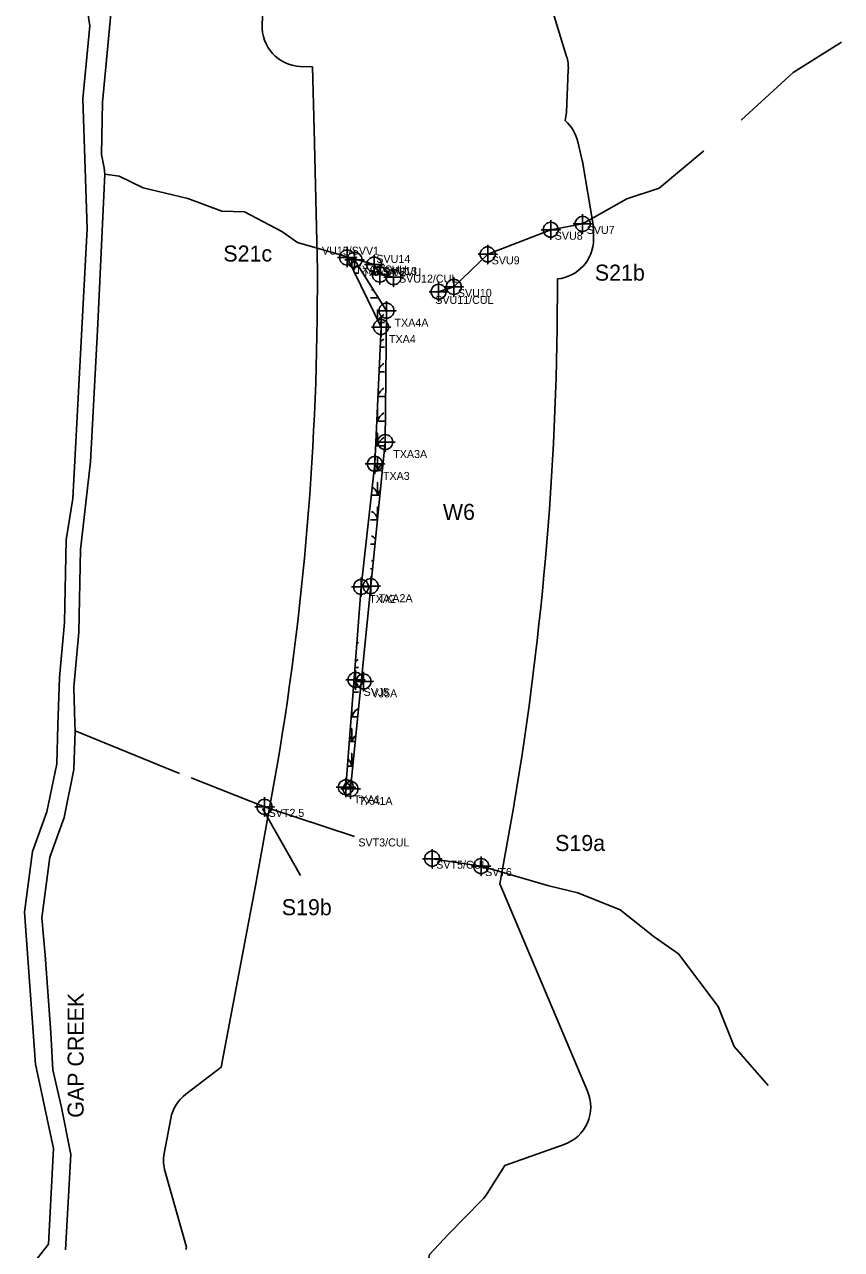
# Model space of a CAD drawing. Extents: x 1253697 to 1278588, y 912189 to 981699.
# Drawn here: x 1262865 to 1263886, y 921586 to 923116 of the extents above; entities that cross this region are included whole.
import ezdxf

# ---------------------------------------------------------------- set-up
doc = ezdxf.new("R2010")
doc.units = 0
for name, color, linetype in [('Default', 7, 'Continuous'), ('Exist Environmental Wetland Boundary', 7, 'Continuous'), ('Exist Environmental Wetland Boundary Cogo Comment', 7, 'Continuous'), ('Exist Environmental Wetland Boundary Cogo Number', 7, 'Continuous'), ('Exist Environmental Wetland Boundary Cogo Point CELL', 7, 'Continuous'), ('Exist Hydro Jurisdictional Stream or Body of Water Mitigable', 7, 'Continuous'), ('Exist Hydro Jurisdictional Stream or Body of Water Mitigable Cogo Comment', 7, 'Continuous'), ('Exist Hydro Jurisdictional Stream or Body of Water Mitigable Cogo Number', 7, 'Continuous'), ('Exist Hydro Jurisdictional Stream or Body of Water Mitigable Cogo Point CELL', 7, 'Continuous'), ('Exist Hydro Swamp or Marsh', 7, 'Continuous')]:
    doc.layers.add(name, color=color, linetype=linetype)

msp = doc.modelspace()

# ---------------------------------------------------------------- linework, layer by layer
at = {"layer": 'Default'}
for p, q in [((1263166.7, 923205.8), (1263162.4, 923115.9)), ((1263166.7, 923205.8), (1263162.4, 923115.9)), ((1263166.7, 923205.8), (1263162.4, 923115.9)), ((1263166.7, 923205.8), (1263162.4, 923115.9)), ((1263542.4, 923006.2), (1263544.8, 923059.2)), ((1263542.4, 923006.2), (1263544.8, 923059.2)), ((1263542.4, 923006.2), (1263544.8, 923059.2)), ((1263542.4, 923006.2), (1263544.8, 923059.2)), ((1263561.8, 922947.5), (1263556.8, 922969.5)), ((1263561.8, 922947.5), (1263556.8, 922969.5)), ((1263561.8, 922947.5), (1263556.8, 922969.5)), ((1263561.8, 922947.5), (1263556.8, 922969.5)), ((1263575.8, 922865.7), (1263562.4, 922944.6)), ((1263575.8, 922865.7), (1263562.4, 922944.6)), ((1263575.8, 922865.7), (1263562.4, 922944.6)), ((1263575.8, 922865.7), (1263562.4, 922944.6)), ((1263576.4, 922847.4), (1263576.5, 922857)), ((1263576.4, 922847.4), (1263576.5, 922857)), ((1263576.4, 922847.4), (1263576.5, 922857)), ((1263576.4, 922847.4), (1263576.5, 922857)), ((1263162.7, 922136.7), (1263210.2, 922053)), ((1263048.1, 921749.3), (1263039.9, 921705.7)), ((1263048.1, 921749.3), (1263039.9, 921705.7)), ((1263048.1, 921749.3), (1263039.9, 921705.7)), ((1263048.1, 921749.3), (1263039.9, 921705.7))]:
    msp.add_line(p, q, dxfattribs=at)
for points in [[(1263542.7, 923076), (1263522.8, 923141.4), (1263517.8, 923304.9), (1263553.3, 923436.7)], [(1263542.7, 923076), (1263522.8, 923141.4), (1263517.8, 923304.9), (1263553.3, 923436.7)], [(1263542.7, 923076), (1263522.8, 923141.4), (1263517.8, 923304.9), (1263553.3, 923436.7)], [(1263542.7, 923076), (1263522.8, 923141.4), (1263517.8, 923304.9), (1263553.3, 923436.7)], [(1263209.9, 923063.5), (1263225, 923062.8), (1263227.4, 922984.9), (1263231.1, 922827.6)], [(1263209.9, 923063.5), (1263225, 923062.8), (1263227.4, 922984.9), (1263231.1, 922827.6)], [(1263209.9, 923063.5), (1263225, 923062.8), (1263227.4, 922984.9), (1263231.1, 922827.6)], [(1263209.9, 923063.5), (1263225, 923062.8), (1263227.4, 922984.9), (1263231.1, 922827.6)], [(1263181.5, 922192.6), (1263153.4, 922037.8), (1263111.1, 921813.4), (1263067, 921779.8)], [(1263181.5, 922192.6), (1263153.4, 922037.8), (1263111.1, 921813.4), (1263067, 921779.8)], [(1263181.5, 922192.6), (1263153.4, 922037.8), (1263111.1, 921813.4), (1263067, 921779.8)], [(1263181.5, 922192.6), (1263153.4, 922037.8), (1263111.1, 921813.4), (1263067, 921779.8)], [(1263569, 921783.6), (1263459.1, 922042.4), (1263477.2, 922142.2)], [(1263569, 921783.6), (1263459.1, 922042.4), (1263477.2, 922142.2)], [(1263569, 921783.6), (1263459.1, 922042.4), (1263477.2, 922142.2)], [(1263569, 921783.6), (1263459.1, 922042.4), (1263477.2, 922142.2)], [(1263443.6, 921655.7), (1263465.6, 921690.5), (1263539.7, 921716.9)], [(1263443.6, 921655.7), (1263465.6, 921690.5), (1263539.7, 921716.9)], [(1263443.6, 921655.7), (1263465.6, 921690.5), (1263539.7, 921716.9)], [(1263443.6, 921655.7), (1263465.6, 921690.5), (1263539.7, 921716.9)], [(1263040.9, 921682.8), (1263067.6, 921588.7), (1263067, 921585.8)], [(1263040.9, 921682.8), (1263067.6, 921588.7), (1263067, 921585.8)], [(1263040.9, 921682.8), (1263067.6, 921588.7), (1263067, 921585.8)], [(1263040.9, 921682.8), (1263067.6, 921588.7), (1263067, 921585.8)], [(1263360.8, 921525), (1263371.4, 921579.3), (1263395, 921604.9), (1263436.9, 921647.3)], [(1263360.8, 921525), (1263371.4, 921579.3), (1263395, 921604.9), (1263436.9, 921647.3)], [(1263360.8, 921525), (1263371.4, 921579.3), (1263395, 921604.9), (1263436.9, 921647.3)], [(1263360.8, 921525), (1263371.4, 921579.3), (1263395, 921604.9), (1263436.9, 921647.3)]]:
    msp.add_lwpolyline(points, dxfattribs=at)
for centre, radius, start, end in [((1263212.3, 923113.4), 50, 177.2304, 267.2304), ((1263212.3, 923113.4), 50, 177.2304, 267.2304), ((1263212.3, 923113.4), 50, 177.2304, 267.2304), ((1263212.3, 923113.4), 50, 177.2304, 267.2304), ((1263494.9, 923061.5), 50, 357.4241, 16.9585), ((1263494.9, 923061.5), 50, 357.4241, 16.9585), ((1263494.9, 923061.5), 50, 357.4241, 16.9585), ((1263494.9, 923061.5), 50, 357.4241, 16.9585), ((1263492.5, 923008.5), 50, 345.4443, 357.4241), ((1263492.5, 923008.5), 50, 345.4443, 357.4241), ((1263492.5, 923008.5), 50, 345.4443, 357.4241), ((1263492.5, 923008.5), 50, 345.4443, 357.4241), ((1263508, 922958.2), 50, 13.0553, 48.9515), ((1263508, 922958.2), 50, 13.0553, 48.9515), ((1263508, 922958.2), 50, 13.0553, 48.9515), ((1263508, 922958.2), 50, 13.0553, 48.9515), ((1263513.1, 922936.2), 50, 9.6038, 13.0553), ((1263513.1, 922936.2), 50, 9.6038, 13.0553), ((1263513.1, 922936.2), 50, 9.6038, 13.0553), ((1263513.1, 922936.2), 50, 9.6038, 13.0553), ((1263526.5, 922857.4), 50, 359.5399, 9.6038), ((1263526.5, 922857.4), 50, 359.5399, 9.6038), ((1263526.5, 922857.4), 50, 359.5399, 9.6038), ((1263526.5, 922857.4), 50, 359.5399, 9.6038), ((1263526.4, 922847.8), 50, 275.5842, 359.5399), ((1263526.4, 922847.8), 50, 275.5842, 359.5399), ((1263526.4, 922847.8), 50, 275.5842, 359.5399), ((1263526.4, 922847.8), 50, 275.5842, 359.5399), ((1259581.3, 922793.3), 3650, 350.5278, 0.538), ((1259581.3, 922793.3), 3650, 350.5278, 0.538), ((1259581.3, 922793.3), 3650, 350.5278, 0.538), ((1259581.3, 922793.3), 3650, 350.5278, 0.538), ((1259581.3, 922793.3), 3950, 350.5223, 0.0692), ((1259581.3, 922793.3), 3950, 350.5223, 0.0692), ((1259581.3, 922793.3), 3950, 350.5223, 0.0692), ((1259581.3, 922793.3), 3950, 350.5223, 0.0692), ((1263428, 922151.1), 50, 349.7208, 350.5223), ((1263428, 922151.1), 50, 349.7208, 350.5223), ((1263428, 922151.1), 50, 349.7208, 350.5223), ((1263428, 922151.1), 50, 349.7208, 350.5223), ((1263097.2, 921740), 50, 127.2474, 169.2814), ((1263097.2, 921740), 50, 127.2474, 169.2814), ((1263097.2, 921740), 50, 127.2474, 169.2814), ((1263097.2, 921740), 50, 127.2474, 169.2814), ((1263522.9, 921764), 50, 289.6297, 22.9949), ((1263522.9, 921764), 50, 289.6297, 22.9949), ((1263522.9, 921764), 50, 289.6297, 22.9949), ((1263522.9, 921764), 50, 289.6297, 22.9949), ((1263089, 921696.4), 50, 169.2814, 195.8576), ((1263089, 921696.4), 50, 169.2814, 195.8576), ((1263089, 921696.4), 50, 169.2814, 195.8576), ((1263089, 921696.4), 50, 169.2814, 195.8576), ((1263401.4, 921682.5), 50, 315.3188, 327.6996), ((1263401.4, 921682.5), 50, 315.3188, 327.6996), ((1263401.4, 921682.5), 50, 315.3188, 327.6996), ((1263401.4, 921682.5), 50, 315.3188, 327.6996)]:
    msp.add_arc(centre, radius, start, end, dxfattribs=at)
at = {"layer": 'Exist Environmental Wetland Boundary'}
msp.add_lwpolyline([(1263268.5, 922824.8), (1263310.8, 922738), (1263303.2, 922567), (1263285.9, 922413.3), (1263266.9, 922163.1), (1263272.8, 922161), (1263297.9, 922414.3), (1263316.1, 922594.3), (1263317.7, 922758.4), (1263277.6, 922821.9)], close=True, dxfattribs=at)
at = {"layer": 'Exist Environmental Wetland Boundary Cogo Point CELL'}
for points in [[(1263268.5, 922836.8), (1263268.5, 922812.8), (1263268.5, 922824.8), (1263280.5, 922824.8), (1263256.5, 922824.8)], [(1263277.6, 922833.9), (1263277.6, 922809.9), (1263277.6, 922821.9), (1263289.6, 922821.9), (1263265.6, 922821.9)], [(1263317.7, 922770.4), (1263317.7, 922746.4), (1263317.7, 922758.4), (1263329.7, 922758.4), (1263305.7, 922758.4)], [(1263310.8, 922750), (1263310.8, 922726), (1263310.8, 922738), (1263322.8, 922738), (1263298.8, 922738)], [(1263316.1, 922606.3), (1263316.1, 922582.3), (1263316.1, 922594.3), (1263328.1, 922594.3), (1263304.1, 922594.3)], [(1263303.2, 922579), (1263303.2, 922555), (1263303.2, 922567), (1263315.2, 922567), (1263291.2, 922567)], [(1263285.9, 922425.3), (1263285.9, 922401.3), (1263285.9, 922413.3), (1263297.9, 922413.3), (1263273.9, 922413.3)], [(1263297.9, 922426.3), (1263297.9, 922402.3), (1263297.9, 922414.3), (1263309.9, 922414.3), (1263285.9, 922414.3)], [(1263279, 922309.2), (1263279, 922285.2), (1263279, 922297.2), (1263291, 922297.2), (1263267, 922297.2)], [(1263289.1, 922307.3), (1263289.1, 922283.3), (1263289.1, 922295.3), (1263301.1, 922295.3), (1263277.1, 922295.3)], [(1263266.9, 922175.1), (1263266.9, 922151.1), (1263266.9, 922163.1), (1263278.9, 922163.1), (1263254.9, 922163.1)], [(1263272.8, 922173), (1263272.8, 922149), (1263272.8, 922161), (1263284.8, 922161), (1263260.8, 922161)]]:
    msp.add_lwpolyline(points, dxfattribs=at)
for centre in [(1263268.5, 922824.8), (1263277.6, 922821.9), (1263317.7, 922758.4), (1263310.8, 922738), (1263316.1, 922594.3), (1263303.2, 922567), (1263285.9, 922413.3), (1263297.9, 922414.3), (1263279, 922297.2), (1263289.1, 922295.3), (1263266.9, 922163.1), (1263272.8, 922161)]:
    msp.add_circle(centre, 9.38, dxfattribs=at)
at = {"layer": 'Exist Hydro Jurisdictional Stream or Body of Water Mitigable'}
msp.add_line((1262928.5, 922233.7), (1263059.2, 922180.1), dxfattribs=at)
for points in [[(1262940.8, 923154.8), (1262946.9, 923114.4), (1262938.1, 923023.2), (1262943.8, 922861.2), (1262925.9, 922523.9), (1262917.2, 922472), (1262915.1, 922369.1), (1262908.9, 922300.3), (1262907, 922240.7), (1262905.6, 922192.4), (1262893.3, 922132.4), (1262875.5, 922082.7), (1262865.3, 922006.9), (1262879.1, 921817.1), (1262901.7, 921711.7), (1262895.1, 921592.4), (1262881.4, 921575)], [(1262916.6, 921585.4), (1262923.2, 921704.6), (1262911.6, 921763.3), (1262900.6, 921810.1), (1262898.4, 921856.2), (1262891.1, 921953.3), (1262886.8, 921999.9), (1262897, 922075.7), (1262914.8, 922125.4), (1262927.1, 922185.3), (1262928.5, 922233.7), (1262928.4, 922242.7), (1262927.1, 922288.2), (1262933.2, 922357), (1262935.4, 922459.9), (1262947.9, 922569.6), (1262956.9, 922742), (1262962, 922849.1), (1262965.7, 922929.1), (1262965, 922936.9), (1262961.7, 922953.6), (1262962.7, 923018.7), (1262975.4, 923151.1)], [(1263886.3, 923093.6), (1263825.7, 923055.7), (1263760.8, 922996.3)], [(1263714.3, 922957.9), (1263658.2, 922911.4), (1263617.9, 922898.1), (1263562.8, 922866.8)], [(1262965.7, 922929.1), (1262983.4, 922926.3), (1263013.7, 922911.9), (1263069.4, 922898.5), (1263112, 922882.8), (1263140.1, 922882), (1263187, 922857.4), (1263206.6, 922843.5), (1263302.2, 922815.9), (1263309.3, 922803.5), (1263326.5, 922800.3)], [(1263382.8, 922782.1), (1263401.8, 922788.1), (1263444.1, 922828.8), (1263522.9, 922859.5), (1263562.8, 922866.8), (1263574.5, 922873.4)], [(1263073.6, 922174.9), (1263165.3, 922138.6), (1263277.5, 922101.7)], [(1263171.3, 922136.6), (1263277.5, 922101.7)], [(1263374.8, 922073.9), (1263435.9, 922064.7), (1263461.8, 922057.1)], [(1263435.9, 922064.7), (1263520.4, 922039.8), (1263556.8, 922031.1), (1263609.5, 922010), (1263652.3, 921976.2), (1263682.6, 921954.9), (1263732.2, 921889.4), (1263752.2, 921839.4), (1263794.8, 921790.6)]]:
    msp.add_lwpolyline(points, dxfattribs=at)
at = {"layer": 'Exist Hydro Jurisdictional Stream or Body of Water Mitigable Cogo Point CELL'}
for points in [[(1263522.9, 922871.5), (1263522.9, 922847.5), (1263522.9, 922859.5), (1263534.9, 922859.5), (1263510.9, 922859.5)], [(1263562.8, 922878.8), (1263562.8, 922854.8), (1263562.8, 922866.8), (1263574.8, 922866.8), (1263550.8, 922866.8)], [(1263444.1, 922840.8), (1263444.1, 922816.8), (1263444.1, 922828.8), (1263456.1, 922828.8), (1263432.1, 922828.8)], [(1263302.2, 922827.9), (1263302.2, 922803.9), (1263302.2, 922815.9), (1263314.2, 922815.9), (1263290.2, 922815.9)], [(1263309.3, 922815.5), (1263309.3, 922791.5), (1263309.3, 922803.5), (1263321.3, 922803.5), (1263297.3, 922803.5)], [(1263326.5, 922812.3), (1263326.5, 922788.3), (1263326.5, 922800.3), (1263338.5, 922800.3), (1263314.5, 922800.3)], [(1263382.8, 922794.1), (1263382.8, 922770.1), (1263382.8, 922782.1), (1263394.8, 922782.1), (1263370.8, 922782.1)], [(1263401.8, 922800.1), (1263401.8, 922776.1), (1263401.8, 922788.1), (1263413.8, 922788.1), (1263389.8, 922788.1)], [(1263165.3, 922150.6), (1263165.3, 922126.6), (1263165.3, 922138.6), (1263177.3, 922138.6), (1263153.3, 922138.6)], [(1263374.8, 922085.9), (1263374.8, 922061.9), (1263374.8, 922073.9), (1263386.8, 922073.9), (1263362.8, 922073.9)], [(1263435.9, 922076.7), (1263435.9, 922052.7), (1263435.9, 922064.7), (1263447.9, 922064.7), (1263423.9, 922064.7)]]:
    msp.add_lwpolyline(points, dxfattribs=at)
for centre in [(1263562.8, 922866.8), (1263522.9, 922859.5), (1263302.2, 922815.9), (1263444.1, 922828.8), (1263309.3, 922803.5), (1263326.5, 922800.3), (1263401.8, 922788.1), (1263382.8, 922782.1), (1263165.3, 922138.6), (1263374.8, 922073.9), (1263435.9, 922064.7)]:
    msp.add_circle(centre, 9.38, dxfattribs=at)
at = {"layer": 'Exist Hydro Swamp or Marsh'}
for p, q in [((1263278, 922805.1), (1263282.8, 922805.1)), ((1263308, 922743.6), (1263315, 922743.6)), ((1263309.6, 922712.8), (1263315, 922712.8)), ((1263308.3, 922682), (1263315, 922682)), ((1263306.9, 922651.2), (1263315, 922651.2)), ((1263297.8, 922497.3), (1263306.3, 922497.3)), ((1263297.8, 922466.6), (1263303.2, 922466.6)), ((1263297.8, 922435.8), (1263300.1, 922435.8)), ((1263280.6, 922343.4), (1263282.8, 922343.4)), ((1263278.3, 922312.7), (1263282.8, 922312.7)), ((1263275.9, 922281.9), (1263282.8, 922281.9))]:
    msp.add_line(p, q, dxfattribs=at)
for points in [[(1263274.2, 922813), (1263274.2, 922820.9), (1263274.2, 922813)], [(1263297.8, 922774.4), (1263306.4, 922774.4), (1263306.4, 922776.3)], [(1263306.4, 922776.3), (1263306.4, 922774.4), (1263307.6, 922774.4)], [(1263306.4, 922746.9), (1263306.4, 922759.4), (1263306.4, 922746.9)], [(1263305.6, 922620.5), (1263306.4, 922620.5), (1263306.4, 922636.2), (1263306.4, 922620.5), (1263315, 922620.5)], [(1263304.2, 922589.7), (1263306.4, 922589.7), (1263306.4, 922605.5), (1263306.4, 922589.7), (1263315, 922589.7)], [(1263302.3, 922558.9), (1263306.4, 922558.9), (1263306.4, 922574.7), (1263306.4, 922558.9), (1263312.5, 922558.9)], [(1263298.9, 922528.1), (1263306.4, 922528.1), (1263306.4, 922543.9), (1263306.4, 922528.1), (1263309.4, 922528.1)], [(1263306.4, 922498.6), (1263306.4, 922513.1), (1263306.4, 922498.6)], [(1263273.6, 922251.1), (1263274.2, 922251.1), (1263274.2, 922259.3)], [(1263274.2, 922259.3), (1263274.2, 922251.1), (1263281.7, 922251.1)], [(1263271.2, 922220.3), (1263274.2, 922220.3), (1263274.2, 922236.1), (1263274.2, 922220.3), (1263278.7, 922220.3)], [(1263268.9, 922189.5), (1263274.2, 922189.5), (1263274.2, 922205.3), (1263274.2, 922189.5), (1263275.6, 922189.5)]]:
    msp.add_lwpolyline(points, dxfattribs=at)
for centre, radius, start, end in [((1263292.4, 922799.1), 19.2, 123.4964, 148.3492), ((1263294.1, 922773.5), 12.3, 47.555, 67.535), ((1263294.1, 922773.5), 12.3, 4.1403, 17.0902), ((1263324.6, 922768.3), 19.2, 157.7735, 161.6222), ((1263324.6, 922737.5), 19.2, 122.1274, 155.6513), ((1263324.6, 922706.7), 19.2, 122.1274, 139.9968), ((1263324.6, 922676), 19.2, 122.1274, 147.229), ((1263324.6, 922645.2), 19.2, 122.1274, 156.5663), ((1263324.6, 922614.4), 19.2, 122.1274, 161.6222), ((1263294.1, 922619.6), 12.3, 4.1403, 19.5311), ((1263294.1, 922588.8), 12.3, 4.1403, 32.6991), ((1263324.6, 922583.6), 19.2, 122.1274, 161.6222), ((1263294.1, 922558), 12.3, 4.1403, 42.7686), ((1263324.6, 922552.8), 19.2, 125.65, 161.6222), ((1263294.1, 922527.2), 12.3, 4.1403, 61.6718), ((1263324.6, 922522.1), 19.2, 139.5273, 161.6222), ((1263294.1, 922496.4), 12.3, 7.186, 67.535), ((1263294.1, 922465.7), 12.3, 37.8921, 67.535), ((1263294.1, 922434.9), 12.3, 56.0416, 67.535), ((1263292.4, 922337.4), 19.2, 122.1274, 125.3342), ((1263292.4, 922306.6), 19.2, 122.1274, 135.1023), ((1263292.4, 922275.8), 19.2, 122.1274, 147.4338), ((1263292.4, 922245), 19.2, 122.1274, 161.6222), ((1263261.9, 922250.2), 12.3, 4.1403, 15.8402), ((1263292.4, 922214.2), 19.2, 132.3343, 161.6222), ((1263261.9, 922219.4), 12.3, 4.1403, 37.1547), ((1263261.9, 922188.6), 12.3, 4.1403, 51.6452), ((1263292.4, 922183.5), 19.2, 148.6156, 161.6222), ((1263261.9, 922157.9), 12.3, 25.5496, 63.9572)]:
    msp.add_arc(centre, radius, start, end, dxfattribs=at)

# ---------------------------------------------------------------- texts
at = {"layer": 'Exist Environmental Wetland Boundary Cogo Comment'}
for s, p in [('TXA5/SVU', (1263278.5, 922804.8)), ('TXA5A/SVU', (1263287.6, 922801.9)), ('TXA4A', (1263327.7, 922738.4)), ('TXA4', (1263320.8, 922718)), ('TXA3A', (1263326.1, 922574.3)), ('TXA3', (1263313.2, 922547)), ('TXA2', (1263295.9, 922393.3)), ('TXA2A', (1263307.9, 922394.3)), ('SVJ5', (1263289, 922277.2)), ('VJ5A', (1263299.1, 922275.3)), ('TXA1', (1263276.9, 922143.1)), ('TXA1A', (1263282.8, 922141))]:
    msp.add_text(s, height=10, dxfattribs=at).set_placement(p)
at = {"layer": 'Exist Environmental Wetland Boundary Cogo Number'}
msp.add_text('W6', height=20, dxfattribs=at).set_placement((1263388.1, 922497.1))
at = {"layer": 'Exist Hydro Jurisdictional Stream or Body of Water Mitigable Cogo Comment'}
for s, p in [('SVU8', (1263527.9, 922847)), ('SVU7', (1263567.8, 922854.3)), ('VU15/SVV1', (1263237, 922828.3)), ('SVU14', (1263305, 922818.1)), ('SVU9', (1263449.1, 922816.3)), ('SVU13', (1263313.4, 922803)), ('SVU12/CUL', (1263333.3, 922793.4)), ('SVU10', (1263406.8, 922775.6)), ('SVU11/CUL', (1263378.6, 922766.9)), ('SVT2.5', (1263170.3, 922126.1)), ('SVT3/CUL', (1263282.5, 922089.2)), ('SVT5/CUL', (1263379.8, 922061.4)), ('SVT6', (1263440.9, 922052.2))]:
    msp.add_text(s, height=10, dxfattribs=at).set_placement(p)
at = {"layer": 'Exist Hydro Jurisdictional Stream or Body of Water Mitigable Cogo Number'}
for s, p in [('S21c', (1263113.8, 922819.8)), ('S21b', (1263578, 922795.9)), ('S19a', (1263528.4, 922083.5)), ('S19b', (1263186.8, 922003.3))]:
    msp.add_text(s, height=20, dxfattribs=at).set_placement(p)
msp.add_text('GAP CREEK', height=20, rotation=90, dxfattribs=at).set_placement((1262939.2, 921750.3))

doc.saveas('drawing.dxf')
